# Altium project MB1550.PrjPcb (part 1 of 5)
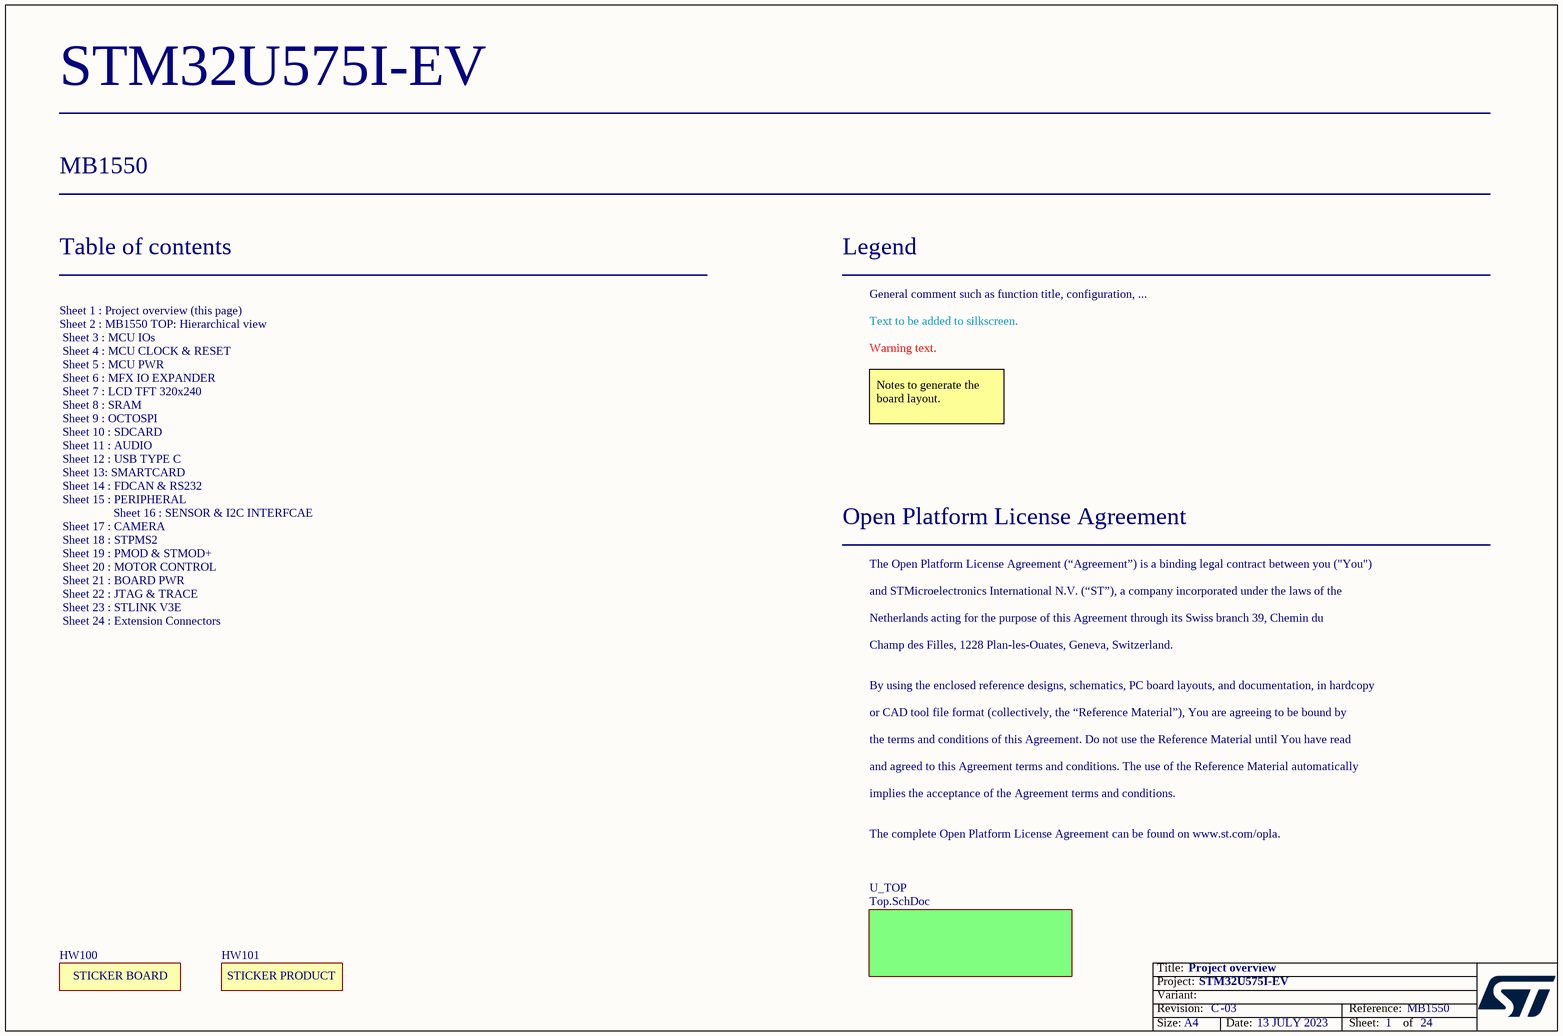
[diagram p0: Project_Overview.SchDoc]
Board_Assembly_Revision: 03; Board_Document_Date: 13 JULY 2023; Board_Name: STM32U575I-EV; Board_PCB_Revision: C; Board_Reference: MB1550
24 sheets, 831 parts. Net scope: flat (ports and power ports of the same name join across sheets).
Board file: MB1550.PcbDoc
Sheets:
  Project_Overview.SchDoc
    U_TOP = Top.SchDoc
      U_AUDIO = AUDIO.SchDoc
      U_BOARD_PWR = BOARD_PWR.SchDoc
      U_Extension_Connector = Extension_Connector.SchDoc
      U_FDCAN_RS232 = FDCAN_RS232.SchDoc
      U_JTAG_TRACE = JTAG_TRACE.SchDoc
      U_MCU_CLOCK_&_RESET = MCU_CLOCK_&_RESET.SchDoc
      U_MCU_IO = MCU_IO.SchDoc
      U_MCU_PWR = MCU_PWR.SchDoc
      U_MOTOR_CONTROL = MOTOR_CONTROL.SchDoc
      U_OCTOSPI = OCTOSPI.SchDoc
      U_PERIPHERAL = PERIPHERAL.SchDoc
      U_PMOD_STMOD+ = PMOD_STMOD+.SchDoc
      U_SDCARD = SDCARD.SchDoc
      U_SMARTCARD = SMARTCARD.SchDoc
      U_SRAM = SRAM.SchDoc
      U_USB_TYPEC = USB_TYPEC.SchDoc
      U_LCD_TFT_320x240 = LCD_TFT_320x240.SchDoc
      U_ST_LINK_V3E = ST_LINK_V3E.SchDoc
      U_Camera = Camera.SchDoc
      U_MFX_IO_expander = MFX_IO_expander.SchDoc
      U_STPMS2 = STPMS2.SchDoc
      U_SENSOR_and_I2C-interface = SENSOR_and_I2C-interface.SchDoc

## Sheet Project_Overview.SchDoc: Project overview
size A4; Date: Not used; ApprovedBy: Not used; CheckedBy: Not used; Author: Not used; CompanyName: STMicroelectronics; DrawnBy: Not used; Engineer: Not used; Organization: Not used; Address1: Not used; Address2: Not used; Address3: Not used; Address4: Not used; DocumentNumber: 1; Revision: Not used; SheetNumber: 1; SheetTotal: 24

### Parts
HW100  STICKER_BOARD  [STICKER_BOARD_25X9]  (value not drawn)  (no BOM)
HW101  STICKER_PRODUCT  [STICKER_PRODUCT_25X9]  (value not drawn)  (no BOM)

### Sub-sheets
U_TOP = Top.SchDoc: no entries

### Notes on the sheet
- Table of contents
- Legend
- General comment such as function title, configuration, ...
- Text to be added to silkscreen.
- Warning text.
- Notes to generate the board layout.
- Open Platform License Agreement
- The Open Platform License Agreement (“Agreement”) is a binding legal contract between you ("You")
- Sheet 1 : Project overview (this page)
  Sheet 2 : MB1550 TOP: Hierarchical view
  Sheet 3 : MCU IOs
  Sheet 4 : MCU CLOCK & RESET
  Sheet 5 : MCU PWR
  Sheet 6 : MFX IO EXPANDER
  Sheet 7 : LCD TFT 320x240
  Sheet 8 : SRAM
  Sheet 9 : OCTOSPI
  Sheet 10 : SDCARD
  Sheet 11 : AUDIO
  Sheet 12 : USB TYPE C
  Sheet 13: SMARTCARD
  Sheet 14 : FDCAN & RS232
  Sheet 15 : PERIPHERAL
  Sheet 16 : SENSOR & I2C INTERFCAE
  Sheet 17 : CAMERA
  Sheet 18 : STPMS2
  Sheet 19 : PMOD & STMOD+
  Sheet 20 : MOTOR CONTROL
  Sheet 21 : BOARD PWR
  Sheet 22 : JTAG & TRACE
  Sheet 23 : STLINK V3E
  Sheet 24 : Extension Connectors
- and STMicroelectronics International N.V. (“ST”), a company incorporated under the laws of the
- Netherlands acting for the purpose of this Agreement through its Swiss branch 39, Chemin du
- Champ des Filles, 1228 Plan-les-Ouates, Geneva, Switzerland.
- By using the enclosed reference designs, schematics, PC board layouts, and documentation, in hardcopy
- or CAD tool file format (collectively, the “Reference Material”), You are agreeing to be bound by
- the terms and conditions of this Agreement. Do not use the Reference Material until You have read
- and agreed to this Agreement terms and conditions. The use of the Reference Material automatically
- implies the acceptance of the Agreement terms and conditions.
- The complete Open Platform License Agreement can be found on www.st.com/opla.

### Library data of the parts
HW100 = MCD-00235: Sticker Board 25x9 mm; Part_Type: Misc; Part_Preference: Recommended
HW101 = MCD-00547: Sticker product 25x9 mm; Part_Type: Misc; Part_Preference: Recommended

## Sheet Top.SchDoc: TOP: Hierarchical view
size A3; Date: Not used; ApprovedBy: Not used; CheckedBy: Not used; Author: Not used; CompanyName: STMicroelectronics; DrawnBy: Not used; Engineer: Not used; Organization: Not used; Address1: Not used; Address2: Not used; Address3: Not used; Address4: Not used; DocumentNumber: 2; Revision: Not used; SheetNumber: 2; SheetTotal: 24
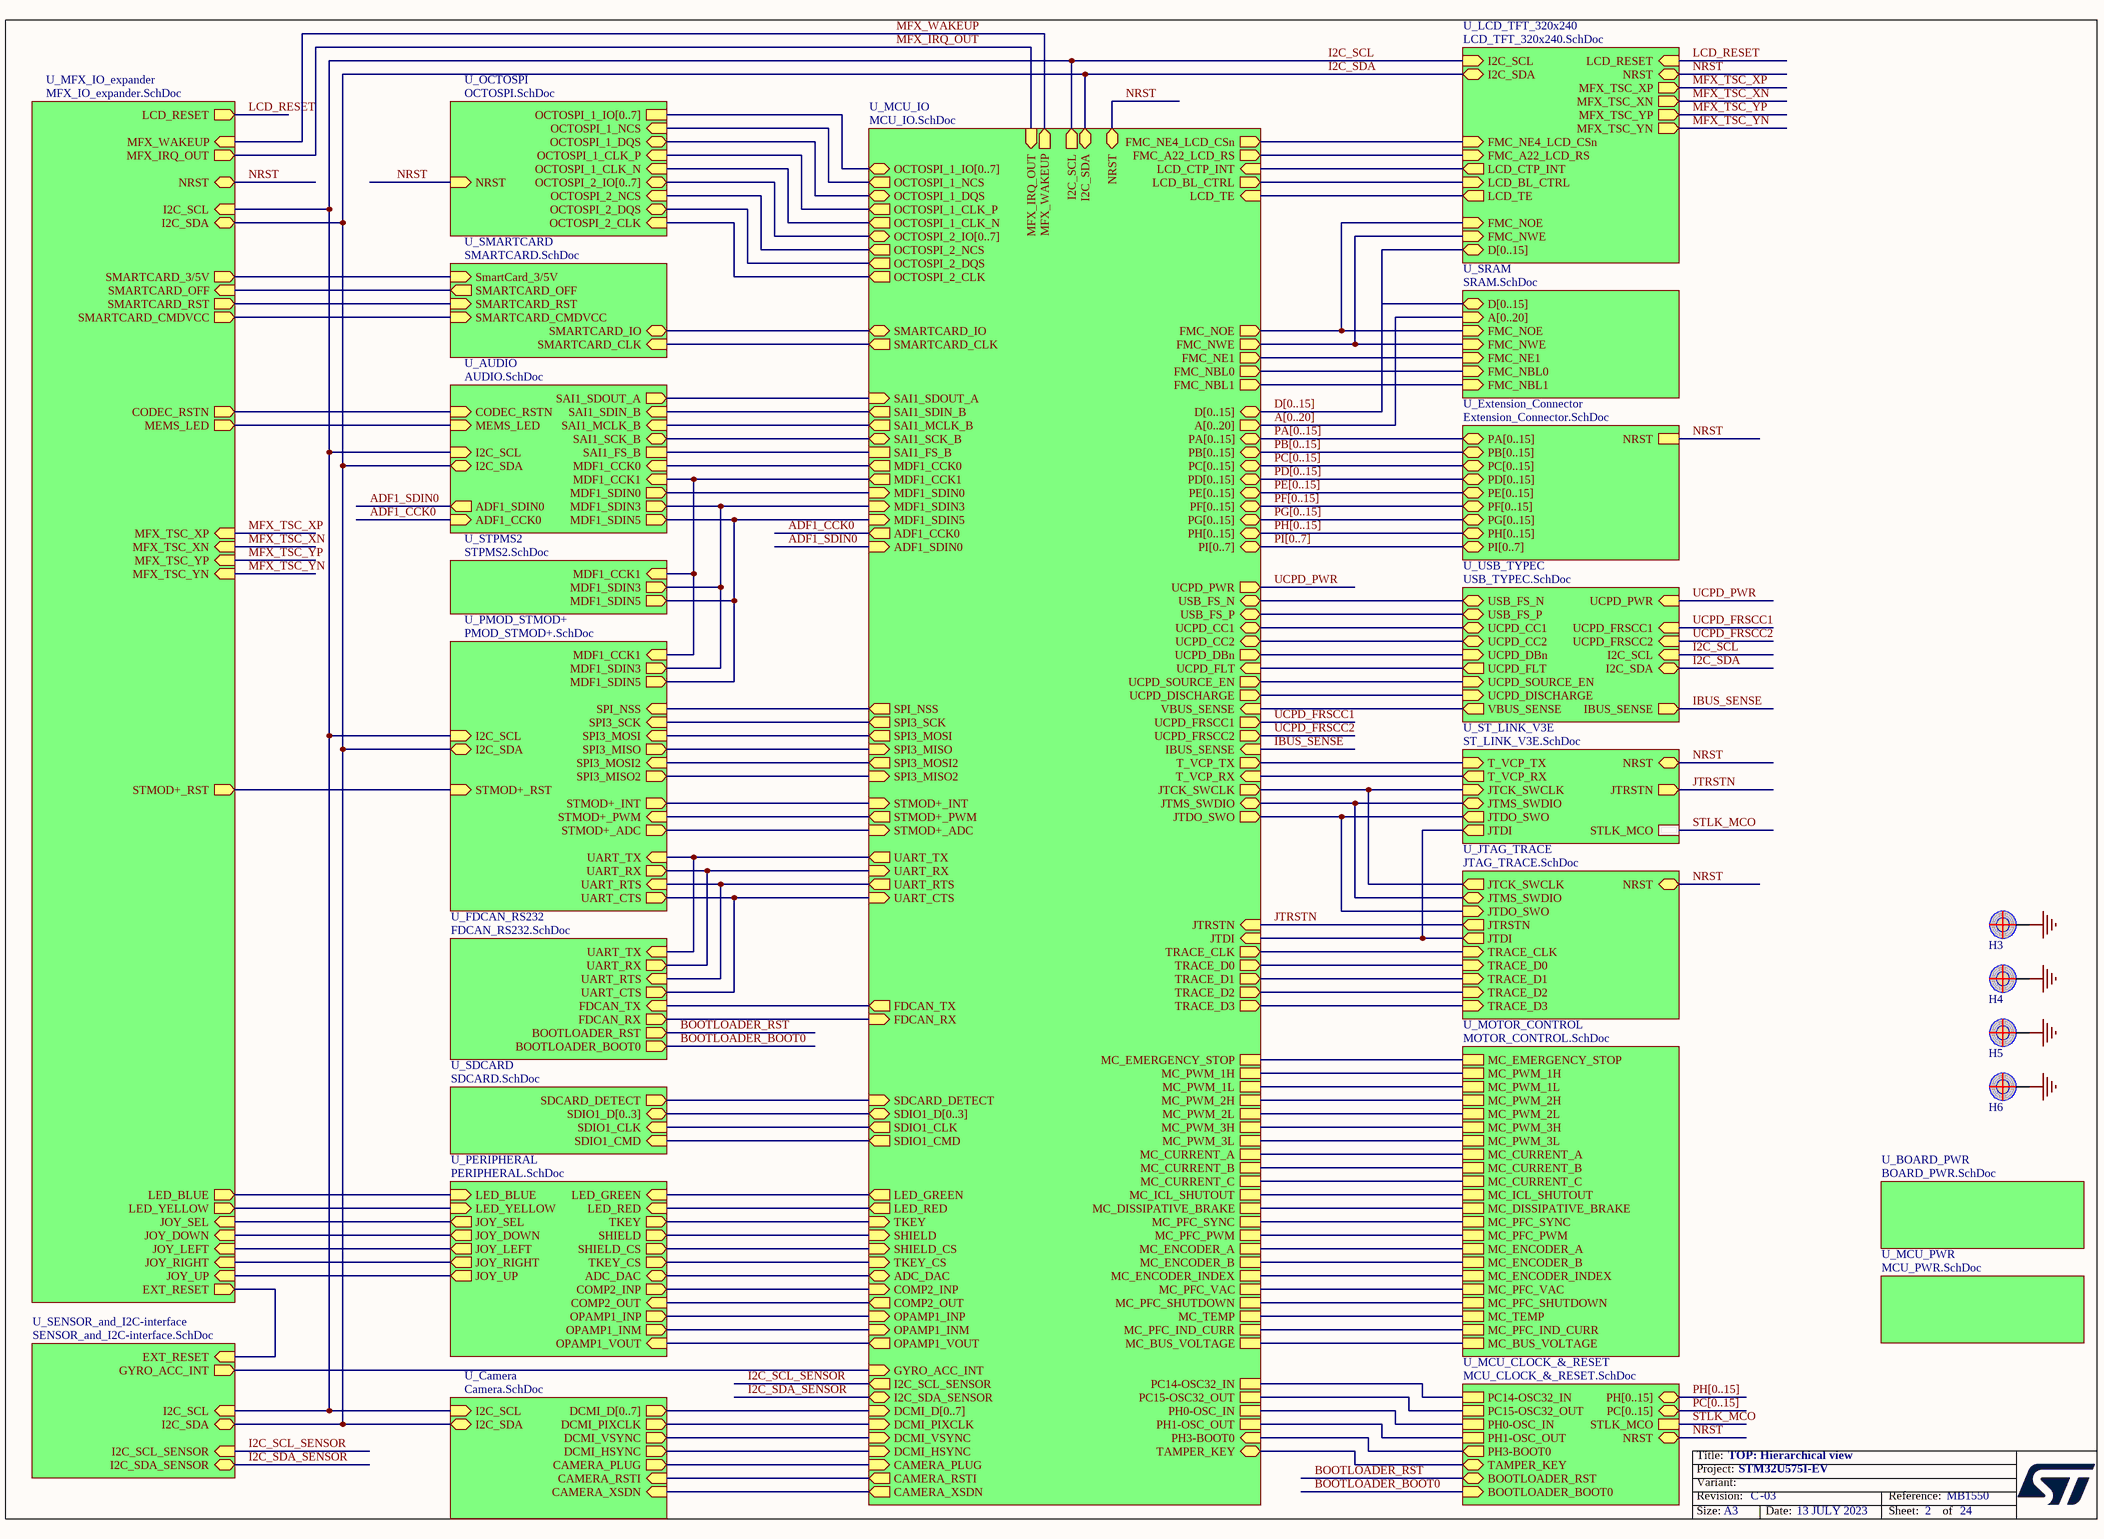
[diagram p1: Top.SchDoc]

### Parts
H3  (no value)  [PTH_M1261-3005-N_3P5X6_M3_H14]  (no BOM)
H4  (no value)  [PTH_M1261-3005-N_3P5X6_M3_H14]  (no BOM)
H5  (no value)  [PTH_M1261-3005-N_3P5X6_M3_H14]  (no BOM)
H6  (no value)  [PTH_M1261-3005-N_3P5X6_M3_H14]  (no BOM)

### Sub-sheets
U_AUDIO = AUDIO.SchDoc: SAI1_MCLK_B (in), SAI1_FS_B, CODEC_RSTN (in), ADF1_SDIN0 (out), MDF1_CCK0 (in), I2C_SCL (in), MEMS_LED (in), SAI1_SDOUT_A (out), MDF1_CCK1 (in), I2C_SDA (bidir), MDF1_SDIN0 (out), MDF1_SDIN5 (out), ADF1_CCK0 (in), SAI1_SCK_B (bidir), MDF1_SDIN3 (out), SAI1_SDIN_B (in)
U_BOARD_PWR = BOARD_PWR.SchDoc: no entries
U_Camera = Camera.SchDoc: DCMI_PIXCLK (out), DCMI_D[0..7] (out), I2C_SDA (bidir), I2C_SCL (in), DCMI_VSYNC (out), CAMERA_PLUG (out), DCMI_HSYNC (out), CAMERA_XSDN (in), CAMERA_RSTI (in)
U_Extension_Connector = Extension_Connector.SchDoc: PA[0..15] (bidir), PB[0..15] (bidir), PC[0..15] (bidir), NRST, PI[0..7] (bidir), PH[0..15] (bidir), PE[0..15] (bidir), PF[0..15] (bidir), PG[0..15] (bidir), PD[0..15] (bidir)
U_FDCAN_RS232 = FDCAN_RS232.SchDoc: BOOTLOADER_BOOT0 (out), BOOTLOADER_RST (out), FDCAN_RX (out), FDCAN_TX (in), UART_RX (out), UART_TX (in), UART_RTS (in), UART_CTS (out)
U_JTAG_TRACE = JTAG_TRACE.SchDoc: JTMS_SWDIO (bidir), JTDI (out), JTDO_SWO (in), JTRSTN (out), TRACE_CLK (in), TRACE_D0 (in), TRACE_D1 (in), TRACE_D2 (in), TRACE_D3 (in), JTCK_SWCLK (out), NRST (bidir)
U_LCD_TFT_320x240 = LCD_TFT_320x240.SchDoc: LCD_RESET (in), LCD_BL_CTRL (in), FMC_NOE (in), FMC_NWE (in), D[0..15] (bidir), LCD_TE (out), FMC_A22_LCD_RS (in), FMC_NE4_LCD_CSn (in), LCD_CTP_INT (out), MFX_TSC_YP (out), I2C_SCL (in), NRST (bidir), MFX_TSC_XP (out), MFX_TSC_YN (out), MFX_TSC_XN (out), I2C_SDA (bidir)
U_MCU_CLOCK_&_RESET = MCU_CLOCK_&_RESET.SchDoc: PC[0..15] (bidir), PH0-OSC_IN, PH1-OSC_OUT, PC14-OSC32_IN, PC15-OSC32_OUT, STLK_MCO, PH[0..15] (bidir), BOOTLOADER_RST (bidir), NRST (bidir), BOOTLOADER_BOOT0 (in), TAMPER_KEY (bidir), PH3-BOOT0 (out)
U_MCU_IO = MCU_IO.SchDoc: PA[0..15] (bidir), PB[0..15] (bidir), PC[0..15] (bidir), PH3-BOOT0 (in), PH0-OSC_IN, PH1-OSC_OUT, PC14-OSC32_IN, PC15-OSC32_OUT, JTMS_SWDIO (bidir), JTDI (in), JTDO_SWO (out), JTRSTN (in), T_VCP_TX (out), T_VCP_RX (in), MFX_IRQ_OUT (in), MFX_WAKEUP (out), D[0..15] (bidir), A[0..20] (out), LCD_BL_CTRL (out), TRACE_D0 (out), SPI3_MISO2 (in), TRACE_D1 (out), TRACE_CLK (out), TRACE_D2 (out), TRACE_D3 (out), SPI3_SCK (out), MC_ICL_SHUTOUT, FMC_NOE (out), FMC_NWE (out), FMC_NE1 (out), FMC_NBL0 (out), FMC_NBL1 (out), MC_PWM_3L, MC_PWM_2L, MC_PWM_1L, MC_PFC_VAC, MC_CURRENT_B, MC_CURRENT_C, MC_PFC_IND_CURR, MC_CURRENT_A, MC_DISSIPATIVE_BRAKE, MC_ENCODER_INDEX, MC_TEMP, SDIO1_CMD (out), SDIO1_CLK (out), SDIO1_D[0..3] (bidir), SDCARD_DETECT (in), MC_PWM_3H, SPI3_MOSI (out), SPI3_MISO (in), SAI1_MCLK_B (out), SAI1_SCK_B (bidir), SAI1_FS_B, MC_PFC_SYNC, MC_PFC_PWM, SPI3_MOSI2 (out), FDCAN_TX (out), FDCAN_RX (in), MC_PFC_SHUTDOWN, MC_PWM_1H, MC_PWM_2H, MC_EMERGENCY_STOP, COMP2_INP (in), COMP2_OUT (out), OPAMP1_INP (in), OPAMP1_VOUT (out), SPI_NSS (out), OPAMP1_INM (in), STMOD+_INT (in), MC_ENCODER_A, MC_ENCODER_B, MC_BUS_VOLTAGE, SMARTCARD_CLK (out), SMARTCARD_IO (bidir), UART_RX (in), UART_TX (out), UCPD_CC2 (bidir), UART_CTS (in), UART_RTS (out), MDF1_CCK1 (out), PI[0..7] (bidir), OCTOSPI_1_NCS (out), MDF1_SDIN0 (in), FMC_NE4_LCD_CSn (out), OCTOSPI_2_IO[0..7] (bidir), OCTOSPI_2_DQS (out), MDF1_SDIN5 (in), PH[0..15] (bidir), ADF1_CCK0 (out), MDF1_CCK0 (out), PG[0..15] (bidir), PF[0..15] (bidir), PE[0..15] (bidir), PD[0..15] (bidir), I2C_SCL (out), LED_GREEN (out), UCPD_SOURCE_EN (out), UCPD_DISCHARGE (out), GYRO_ACC_INT (in), OCTOSPI_1_CLK_P (out), I2C_SCL_SENSOR (out), USB_FS_P (bidir), TKEY (in), ADC_DAC (bidir), NRST (bidir), TAMPER_KEY (bidir), SHIELD (in), MDF1_SDIN3 (in), UCPD_DBn (out), UCPD_FLT (in), STMOD+_PWM (out), DCMI_HSYNC (in), UCPD_CC1 (bidir), I2C_SDA (bidir), TKEY_CS (in), STMOD+_ADC (in), FMC_A22_LCD_RS (out), SAI1_SDOUT_A (in), USB_FS_N (bidir), JTCK_SWCLK (out), OCTOSPI_1_DQS (bidir), SHIELD_CS (in), OCTOSPI_1_IO[0..7] (bidir), DCMI_D[0..7] (in), LCD_CTP_INT (in), SAI1_SDIN_B (out), VBUS_SENSE (in), LED_RED (out), CAMERA_XSDN (out), DCMI_VSYNC (in), UCPD_FRSCC1 (out), I2C_SDA_SENSOR (bidir), OCTOSPI_2_NCS (out), UCPD_PWR (out), UCPD_FRSCC2 (out), OCTOSPI_1_CLK_N (out), CAMERA_PLUG (in), OCTOSPI_2_CLK (out), ADF1_SDIN0 (in), LCD_TE (in), DCMI_PIXCLK (in), IBUS_SENSE (in), CAMERA_RSTI (out)
U_MCU_PWR = MCU_PWR.SchDoc: no entries
U_MFX_IO_expander = MFX_IO_expander.SchDoc: MFX_IRQ_OUT (out), MFX_WAKEUP (in), JOY_SEL (in), JOY_DOWN (in), JOY_LEFT (in), JOY_RIGHT (in), JOY_UP (in), LCD_RESET (out), EXT_RESET (out), STMOD+_RST (out), CODEC_RSTN (out), SMARTCARD_3/5V (out), SMARTCARD_CMDVCC (out), SMARTCARD_RST (out), SMARTCARD_OFF (in), MEMS_LED (out), MFX_TSC_XP (in), MFX_TSC_XN (in), MFX_TSC_YP (in), MFX_TSC_YN (in), LED_YELLOW (out), I2C_SCL (in), NRST (bidir), I2C_SDA (bidir), LED_BLUE (out)
U_MOTOR_CONTROL = MOTOR_CONTROL.SchDoc: MC_EMERGENCY_STOP, MC_PWM_1H, MC_PWM_1L, MC_PWM_2H, MC_PWM_2L, MC_PWM_3H, MC_PWM_3L, MC_CURRENT_A, MC_CURRENT_B, MC_CURRENT_C, MC_ICL_SHUTOUT, MC_DISSIPATIVE_BRAKE, MC_PFC_SYNC, MC_PFC_PWM, MC_ENCODER_A, MC_ENCODER_B, MC_ENCODER_INDEX, MC_PFC_VAC, MC_PFC_SHUTDOWN, MC_TEMP, MC_PFC_IND_CURR, MC_BUS_VOLTAGE
U_OCTOSPI = OCTOSPI.SchDoc: NRST (in), OCTOSPI_1_IO[0..7], OCTOSPI_1_NCS (in), OCTOSPI_2_NCS (in), OCTOSPI_2_IO[0..7] (bidir), OCTOSPI_2_CLK (in), OCTOSPI_1_CLK_N (in), OCTOSPI_1_CLK_P (in), OCTOSPI_1_DQS (bidir), OCTOSPI_2_DQS (bidir)
U_PERIPHERAL = PERIPHERAL.SchDoc: JOY_SEL (out), JOY_DOWN (out), JOY_LEFT (out), JOY_RIGHT (out), JOY_UP (out), COMP2_INP (out), OPAMP1_VOUT (in), OPAMP1_INM (out), OPAMP1_INP (out), COMP2_OUT (in), TKEY (out), ADC_DAC (bidir), LED_YELLOW (in), TKEY_CS (out), LED_BLUE (in), LED_GREEN (in), SHIELD (out), SHIELD_CS (out), LED_RED (in)
U_PMOD_STMOD+ = PMOD_STMOD+.SchDoc: STMOD+_INT (out), SPI_NSS (in), SPI3_MOSI (in), SPI3_MISO (out), SPI3_SCK (in), STMOD+_RST (in), SPI3_MOSI2 (in), SPI3_MISO2 (out), UART_RX (out), UART_TX (in), UART_RTS (in), UART_CTS (out), I2C_SCL (in), STMOD+_ADC (out), I2C_SDA (bidir), MDF1_SDIN5 (out), MDF1_SDIN3 (out), STMOD+_PWM (in), MDF1_CCK1 (in)
U_SDCARD = SDCARD.SchDoc: SDIO1_CMD (in), SDIO1_CLK (in), SDCARD_DETECT (out), SDIO1_D[0..3] (bidir)
U_SENSOR_and_I2C-interface = SENSOR_and_I2C-interface.SchDoc: I2C_SCL (in), EXT_RESET (in), GYRO_ACC_INT (out), I2C_SCL_SENSOR (in), I2C_SDA_SENSOR (bidir), I2C_SDA (bidir)
U_SMARTCARD = SMARTCARD.SchDoc: SmartCard_3/5V (in), SMARTCARD_IO (bidir), SMARTCARD_RST (in), SMARTCARD_CLK (in), SMARTCARD_OFF (out), SMARTCARD_CMDVCC (in)
U_SRAM = SRAM.SchDoc: FMC_NWE (in), FMC_NOE (in), FMC_NE1 (in), D[0..15] (bidir), A[0..20] (in), FMC_NBL0 (in), FMC_NBL1 (in)
U_ST_LINK_V3E = ST_LINK_V3E.SchDoc: STLK_MCO, JTMS_SWDIO (bidir), JTDO_SWO (out), JTCK_SWCLK (in), JTRSTN (out), T_VCP_RX (out), JTDI (out), T_VCP_TX (in), NRST (bidir)
U_STPMS2 = STPMS2.SchDoc: MDF1_CCK1 (in), MDF1_SDIN3 (out), MDF1_SDIN5 (out)
U_USB_TYPEC = USB_TYPEC.SchDoc: USB_FS_N (bidir), USB_FS_P (bidir), UCPD_PWR (in), I2C_SCL (in), I2C_SDA (bidir), UCPD_DISCHARGE (in), UCPD_DBn (in), UCPD_CC1 (bidir), UCPD_FRSCC2 (in), VBUS_SENSE (out), UCPD_FRSCC1 (in), UCPD_SOURCE_EN (in), IBUS_SENSE (out), UCPD_CC2 (bidir), UCPD_FLT (out)

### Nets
GND: H3.1 H4.1 H5.1 H6.1
ADF1_CCK0: sheet U_AUDIO/ADF1_CCK0, sheet U_MCU_IO/ADF1_CCK0
ADF1_SDIN0: sheet U_AUDIO/ADF1_SDIN0, sheet U_MCU_IO/ADF1_SDIN0
BOOTLOADER_BOOT0: sheet U_FDCAN_RS232/BOOTLOADER_BOOT0, sheet U_MCU_CLOCK_&_RESET/BOOTLOADER_BOOT0
BOOTLOADER_RST: sheet U_FDCAN_RS232/BOOTLOADER_RST, sheet U_MCU_CLOCK_&_RESET/BOOTLOADER_RST
I2C_SCL: sheet U_AUDIO/I2C_SCL, sheet U_MCU_IO/I2C_SCL, sheet U_PMOD_STMOD+/I2C_SCL, sheet U_USB_TYPEC/I2C_SCL, sheet U_LCD_TFT_320x240/I2C_SCL, sheet U_Camera/I2C_SCL, sheet U_MFX_IO_expander/I2C_SCL, sheet U_SENSOR_and_I2C-interface/I2C_SCL
I2C_SCL_SENSOR: sheet U_MCU_IO/I2C_SCL_SENSOR, sheet U_SENSOR_and_I2C-interface/I2C_SCL_SENSOR
I2C_SDA: sheet U_AUDIO/I2C_SDA, sheet U_MCU_IO/I2C_SDA, sheet U_PMOD_STMOD+/I2C_SDA, sheet U_USB_TYPEC/I2C_SDA, sheet U_LCD_TFT_320x240/I2C_SDA, sheet U_Camera/I2C_SDA, sheet U_MFX_IO_expander/I2C_SDA, sheet U_SENSOR_and_I2C-interface/I2C_SDA
I2C_SDA_SENSOR: sheet U_MCU_IO/I2C_SDA_SENSOR, sheet U_SENSOR_and_I2C-interface/I2C_SDA_SENSOR
IBUS_SENSE: sheet U_MCU_IO/IBUS_SENSE, sheet U_USB_TYPEC/IBUS_SENSE
JTRSTN: sheet U_JTAG_TRACE/JTRSTN, sheet U_MCU_IO/JTRSTN, sheet U_ST_LINK_V3E/JTRSTN
LCD_RESET: sheet U_LCD_TFT_320x240/LCD_RESET, sheet U_MFX_IO_expander/LCD_RESET
MFX_IRQ_OUT: sheet U_MCU_IO/MFX_IRQ_OUT, sheet U_MFX_IO_expander/MFX_IRQ_OUT
MFX_TSC_XN: sheet U_LCD_TFT_320x240/MFX_TSC_XN, sheet U_MFX_IO_expander/MFX_TSC_XN
MFX_TSC_XP: sheet U_LCD_TFT_320x240/MFX_TSC_XP, sheet U_MFX_IO_expander/MFX_TSC_XP
MFX_TSC_YN: sheet U_LCD_TFT_320x240/MFX_TSC_YN, sheet U_MFX_IO_expander/MFX_TSC_YN
MFX_TSC_YP: sheet U_LCD_TFT_320x240/MFX_TSC_YP, sheet U_MFX_IO_expander/MFX_TSC_YP
MFX_WAKEUP: sheet U_MCU_IO/MFX_WAKEUP, sheet U_MFX_IO_expander/MFX_WAKEUP
NRST: sheet U_Extension_Connector/NRST, sheet U_JTAG_TRACE/NRST, sheet U_MCU_CLOCK_&_RESET/NRST, sheet U_MCU_IO/NRST, sheet U_OCTOSPI/NRST, sheet U_LCD_TFT_320x240/NRST, sheet U_ST_LINK_V3E/NRST, sheet U_MFX_IO_expander/NRST
STLK_MCO: sheet U_MCU_CLOCK_&_RESET/STLK_MCO, sheet U_ST_LINK_V3E/STLK_MCO
UCPD_FRSCC1: sheet U_MCU_IO/UCPD_FRSCC1, sheet U_USB_TYPEC/UCPD_FRSCC1
UCPD_FRSCC2: sheet U_MCU_IO/UCPD_FRSCC2, sheet U_USB_TYPEC/UCPD_FRSCC2
UCPD_PWR: sheet U_MCU_IO/UCPD_PWR, sheet U_USB_TYPEC/UCPD_PWR
(unnamed): sheet U_AUDIO/SAI1_MCLK_B, sheet U_MCU_IO/SAI1_MCLK_B
(unnamed): sheet U_AUDIO/SAI1_FS_B, sheet U_MCU_IO/SAI1_FS_B  [a separate net that carries the same name]
(unnamed): sheet U_AUDIO/CODEC_RSTN, sheet U_MFX_IO_expander/CODEC_RSTN  [a separate net that carries the same name]
(unnamed): sheet U_AUDIO/MDF1_CCK0, sheet U_MCU_IO/MDF1_CCK0  [a separate net that carries the same name]
(unnamed): sheet U_AUDIO/MEMS_LED, sheet U_MFX_IO_expander/MEMS_LED  [a separate net that carries the same name]
(unnamed): sheet U_AUDIO/SAI1_SDOUT_A, sheet U_MCU_IO/SAI1_SDOUT_A  [a separate net that carries the same name]
(unnamed): sheet U_AUDIO/MDF1_CCK1, sheet U_MCU_IO/MDF1_CCK1, sheet U_PMOD_STMOD+/MDF1_CCK1, sheet U_STPMS2/MDF1_CCK1  [a separate net that carries the same name]
(unnamed): sheet U_AUDIO/MDF1_SDIN0, sheet U_MCU_IO/MDF1_SDIN0  [a separate net that carries the same name]
(unnamed): sheet U_AUDIO/MDF1_SDIN5, sheet U_MCU_IO/MDF1_SDIN5, sheet U_PMOD_STMOD+/MDF1_SDIN5, sheet U_STPMS2/MDF1_SDIN5  [a separate net that carries the same name]
(unnamed): sheet U_AUDIO/SAI1_SCK_B, sheet U_MCU_IO/SAI1_SCK_B  [a separate net that carries the same name]
(unnamed): sheet U_AUDIO/MDF1_SDIN3, sheet U_MCU_IO/MDF1_SDIN3, sheet U_PMOD_STMOD+/MDF1_SDIN3, sheet U_STPMS2/MDF1_SDIN3  [a separate net that carries the same name]
(unnamed): sheet U_AUDIO/SAI1_SDIN_B, sheet U_MCU_IO/SAI1_SDIN_B  [a separate net that carries the same name]
(unnamed): sheet U_FDCAN_RS232/FDCAN_RX, sheet U_MCU_IO/FDCAN_RX  [a separate net that carries the same name]
(unnamed): sheet U_FDCAN_RS232/FDCAN_TX, sheet U_MCU_IO/FDCAN_TX  [a separate net that carries the same name]
(unnamed): sheet U_FDCAN_RS232/UART_RX, sheet U_MCU_IO/UART_RX, sheet U_PMOD_STMOD+/UART_RX  [a separate net that carries the same name]
(unnamed): sheet U_FDCAN_RS232/UART_TX, sheet U_MCU_IO/UART_TX, sheet U_PMOD_STMOD+/UART_TX  [a separate net that carries the same name]
(unnamed): sheet U_FDCAN_RS232/UART_RTS, sheet U_MCU_IO/UART_RTS, sheet U_PMOD_STMOD+/UART_RTS  [a separate net that carries the same name]
(unnamed): sheet U_FDCAN_RS232/UART_CTS, sheet U_MCU_IO/UART_CTS, sheet U_PMOD_STMOD+/UART_CTS  [a separate net that carries the same name]
(unnamed): sheet U_JTAG_TRACE/JTMS_SWDIO, sheet U_MCU_IO/JTMS_SWDIO, sheet U_ST_LINK_V3E/JTMS_SWDIO  [a separate net that carries the same name]
(unnamed): sheet U_JTAG_TRACE/JTDI, sheet U_MCU_IO/JTDI, sheet U_ST_LINK_V3E/JTDI  [a separate net that carries the same name]
(unnamed): sheet U_JTAG_TRACE/JTDO_SWO, sheet U_MCU_IO/JTDO_SWO, sheet U_ST_LINK_V3E/JTDO_SWO  [a separate net that carries the same name]
(unnamed): sheet U_JTAG_TRACE/TRACE_CLK, sheet U_MCU_IO/TRACE_CLK  [a separate net that carries the same name]
(unnamed): sheet U_JTAG_TRACE/TRACE_D0, sheet U_MCU_IO/TRACE_D0  [a separate net that carries the same name]
(unnamed): sheet U_JTAG_TRACE/TRACE_D1, sheet U_MCU_IO/TRACE_D1  [a separate net that carries the same name]
(unnamed): sheet U_JTAG_TRACE/TRACE_D2, sheet U_MCU_IO/TRACE_D2  [a separate net that carries the same name]
(unnamed): sheet U_JTAG_TRACE/TRACE_D3, sheet U_MCU_IO/TRACE_D3  [a separate net that carries the same name]
(unnamed): sheet U_JTAG_TRACE/JTCK_SWCLK, sheet U_MCU_IO/JTCK_SWCLK, sheet U_ST_LINK_V3E/JTCK_SWCLK  [a separate net that carries the same name]
(unnamed): sheet U_MCU_CLOCK_&_RESET/PH0-OSC_IN, sheet U_MCU_IO/PH0-OSC_IN  [a separate net that carries the same name]
(unnamed): sheet U_MCU_CLOCK_&_RESET/PH1-OSC_OUT, sheet U_MCU_IO/PH1-OSC_OUT  [a separate net that carries the same name]
(unnamed): sheet U_MCU_CLOCK_&_RESET/PC14-OSC32_IN, sheet U_MCU_IO/PC14-OSC32_IN  [a separate net that carries the same name]
(unnamed): sheet U_MCU_CLOCK_&_RESET/PC15-OSC32_OUT, sheet U_MCU_IO/PC15-OSC32_OUT  [a separate net that carries the same name]
(unnamed): sheet U_MCU_CLOCK_&_RESET/TAMPER_KEY, sheet U_MCU_IO/TAMPER_KEY  [a separate net that carries the same name]
(unnamed): sheet U_MCU_CLOCK_&_RESET/PH3-BOOT0, sheet U_MCU_IO/PH3-BOOT0  [a separate net that carries the same name]
(unnamed): sheet U_MCU_IO/T_VCP_TX, sheet U_ST_LINK_V3E/T_VCP_TX  [a separate net that carries the same name]
(unnamed): sheet U_MCU_IO/T_VCP_RX, sheet U_ST_LINK_V3E/T_VCP_RX  [a separate net that carries the same name]
(unnamed): sheet U_MCU_IO/LCD_BL_CTRL, sheet U_LCD_TFT_320x240/LCD_BL_CTRL  [a separate net that carries the same name]
(unnamed): sheet U_MCU_IO/SPI3_MISO2, sheet U_PMOD_STMOD+/SPI3_MISO2  [a separate net that carries the same name]
(unnamed): sheet U_MCU_IO/SPI3_SCK, sheet U_PMOD_STMOD+/SPI3_SCK  [a separate net that carries the same name]
(unnamed): sheet U_MCU_IO/MC_ICL_SHUTOUT, sheet U_MOTOR_CONTROL/MC_ICL_SHUTOUT  [a separate net that carries the same name]
(unnamed): sheet U_MCU_IO/FMC_NOE, sheet U_SRAM/FMC_NOE, sheet U_LCD_TFT_320x240/FMC_NOE  [a separate net that carries the same name]
(unnamed): sheet U_MCU_IO/FMC_NWE, sheet U_SRAM/FMC_NWE, sheet U_LCD_TFT_320x240/FMC_NWE  [a separate net that carries the same name]
(unnamed): sheet U_MCU_IO/FMC_NE1, sheet U_SRAM/FMC_NE1  [a separate net that carries the same name]
(unnamed): sheet U_MCU_IO/FMC_NBL0, sheet U_SRAM/FMC_NBL0  [a separate net that carries the same name]
(unnamed): sheet U_MCU_IO/FMC_NBL1, sheet U_SRAM/FMC_NBL1  [a separate net that carries the same name]
(unnamed): sheet U_MCU_IO/MC_PWM_3L, sheet U_MOTOR_CONTROL/MC_PWM_3L  [a separate net that carries the same name]
(unnamed): sheet U_MCU_IO/MC_PWM_2L, sheet U_MOTOR_CONTROL/MC_PWM_2L  [a separate net that carries the same name]
(unnamed): sheet U_MCU_IO/MC_PWM_1L, sheet U_MOTOR_CONTROL/MC_PWM_1L  [a separate net that carries the same name]
(unnamed): sheet U_MCU_IO/MC_PFC_VAC, sheet U_MOTOR_CONTROL/MC_PFC_VAC  [a separate net that carries the same name]
(unnamed): sheet U_MCU_IO/MC_CURRENT_B, sheet U_MOTOR_CONTROL/MC_CURRENT_B  [a separate net that carries the same name]
(unnamed): sheet U_MCU_IO/MC_CURRENT_C, sheet U_MOTOR_CONTROL/MC_CURRENT_C  [a separate net that carries the same name]
(unnamed): sheet U_MCU_IO/MC_PFC_IND_CURR, sheet U_MOTOR_CONTROL/MC_PFC_IND_CURR  [a separate net that carries the same name]
(unnamed): sheet U_MCU_IO/MC_CURRENT_A, sheet U_MOTOR_CONTROL/MC_CURRENT_A  [a separate net that carries the same name]
(unnamed): sheet U_MCU_IO/MC_DISSIPATIVE_BRAKE, sheet U_MOTOR_CONTROL/MC_DISSIPATIVE_BRAKE  [a separate net that carries the same name]
(unnamed): sheet U_MCU_IO/MC_ENCODER_INDEX, sheet U_MOTOR_CONTROL/MC_ENCODER_INDEX  [a separate net that carries the same name]
(unnamed): sheet U_MCU_IO/MC_TEMP, sheet U_MOTOR_CONTROL/MC_TEMP  [a separate net that carries the same name]
(unnamed): sheet U_MCU_IO/SDIO1_CMD, sheet U_SDCARD/SDIO1_CMD  [a separate net that carries the same name]
(unnamed): sheet U_MCU_IO/SDIO1_CLK, sheet U_SDCARD/SDIO1_CLK  [a separate net that carries the same name]
(unnamed): sheet U_MCU_IO/SDCARD_DETECT, sheet U_SDCARD/SDCARD_DETECT  [a separate net that carries the same name]
(unnamed): sheet U_MCU_IO/MC_PWM_3H, sheet U_MOTOR_CONTROL/MC_PWM_3H  [a separate net that carries the same name]
(unnamed): sheet U_MCU_IO/SPI3_MOSI, sheet U_PMOD_STMOD+/SPI3_MOSI  [a separate net that carries the same name]
(unnamed): sheet U_MCU_IO/SPI3_MISO, sheet U_PMOD_STMOD+/SPI3_MISO  [a separate net that carries the same name]
(unnamed): sheet U_MCU_IO/MC_PFC_SYNC, sheet U_MOTOR_CONTROL/MC_PFC_SYNC  [a separate net that carries the same name]
(unnamed): sheet U_MCU_IO/MC_PFC_PWM, sheet U_MOTOR_CONTROL/MC_PFC_PWM  [a separate net that carries the same name]
(unnamed): sheet U_MCU_IO/SPI3_MOSI2, sheet U_PMOD_STMOD+/SPI3_MOSI2  [a separate net that carries the same name]
(unnamed): sheet U_MCU_IO/MC_PFC_SHUTDOWN, sheet U_MOTOR_CONTROL/MC_PFC_SHUTDOWN  [a separate net that carries the same name]
(unnamed): sheet U_MCU_IO/MC_PWM_1H, sheet U_MOTOR_CONTROL/MC_PWM_1H  [a separate net that carries the same name]
(unnamed): sheet U_MCU_IO/MC_PWM_2H, sheet U_MOTOR_CONTROL/MC_PWM_2H  [a separate net that carries the same name]
(unnamed): sheet U_MCU_IO/MC_EMERGENCY_STOP, sheet U_MOTOR_CONTROL/MC_EMERGENCY_STOP  [a separate net that carries the same name]
(unnamed): sheet U_MCU_IO/COMP2_INP, sheet U_PERIPHERAL/COMP2_INP  [a separate net that carries the same name]
(unnamed): sheet U_MCU_IO/COMP2_OUT, sheet U_PERIPHERAL/COMP2_OUT  [a separate net that carries the same name]
(unnamed): sheet U_MCU_IO/OPAMP1_INP, sheet U_PERIPHERAL/OPAMP1_INP  [a separate net that carries the same name]
(unnamed): sheet U_MCU_IO/OPAMP1_VOUT, sheet U_PERIPHERAL/OPAMP1_VOUT  [a separate net that carries the same name]
(unnamed): sheet U_MCU_IO/SPI_NSS, sheet U_PMOD_STMOD+/SPI_NSS  [a separate net that carries the same name]
(unnamed): sheet U_MCU_IO/OPAMP1_INM, sheet U_PERIPHERAL/OPAMP1_INM  [a separate net that carries the same name]
(unnamed): sheet U_MCU_IO/STMOD+_INT, sheet U_PMOD_STMOD+/STMOD+_INT  [a separate net that carries the same name]
(unnamed): sheet U_MCU_IO/MC_ENCODER_A, sheet U_MOTOR_CONTROL/MC_ENCODER_A  [a separate net that carries the same name]
(unnamed): sheet U_MCU_IO/MC_ENCODER_B, sheet U_MOTOR_CONTROL/MC_ENCODER_B  [a separate net that carries the same name]
(unnamed): sheet U_MCU_IO/MC_BUS_VOLTAGE, sheet U_MOTOR_CONTROL/MC_BUS_VOLTAGE  [a separate net that carries the same name]
(unnamed): sheet U_MCU_IO/SMARTCARD_CLK, sheet U_SMARTCARD/SMARTCARD_CLK  [a separate net that carries the same name]
(unnamed): sheet U_MCU_IO/SMARTCARD_IO, sheet U_SMARTCARD/SMARTCARD_IO  [a separate net that carries the same name]
(unnamed): sheet U_MCU_IO/UCPD_CC2, sheet U_USB_TYPEC/UCPD_CC2  [a separate net that carries the same name]
(unnamed): sheet U_MCU_IO/OCTOSPI_1_NCS, sheet U_OCTOSPI/OCTOSPI_1_NCS  [a separate net that carries the same name]
(unnamed): sheet U_MCU_IO/FMC_NE4_LCD_CSn, sheet U_LCD_TFT_320x240/FMC_NE4_LCD_CSn  [a separate net that carries the same name]
(unnamed): sheet U_MCU_IO/OCTOSPI_2_DQS, sheet U_OCTOSPI/OCTOSPI_2_DQS  [a separate net that carries the same name]
(unnamed): sheet U_MCU_IO/LED_GREEN, sheet U_PERIPHERAL/LED_GREEN  [a separate net that carries the same name]
(unnamed): sheet U_MCU_IO/UCPD_SOURCE_EN, sheet U_USB_TYPEC/UCPD_SOURCE_EN  [a separate net that carries the same name]
(unnamed): sheet U_MCU_IO/UCPD_DISCHARGE, sheet U_USB_TYPEC/UCPD_DISCHARGE  [a separate net that carries the same name]
(unnamed): sheet U_MCU_IO/GYRO_ACC_INT, sheet U_SENSOR_and_I2C-interface/GYRO_ACC_INT  [a separate net that carries the same name]
(unnamed): sheet U_MCU_IO/OCTOSPI_1_CLK_P, sheet U_OCTOSPI/OCTOSPI_1_CLK_P  [a separate net that carries the same name]
(unnamed): sheet U_MCU_IO/USB_FS_P, sheet U_USB_TYPEC/USB_FS_P  [a separate net that carries the same name]
(unnamed): sheet U_MCU_IO/TKEY, sheet U_PERIPHERAL/TKEY  [a separate net that carries the same name]
(unnamed): sheet U_MCU_IO/ADC_DAC, sheet U_PERIPHERAL/ADC_DAC  [a separate net that carries the same name]
(unnamed): sheet U_MCU_IO/SHIELD, sheet U_PERIPHERAL/SHIELD  [a separate net that carries the same name]
(unnamed): sheet U_MCU_IO/UCPD_DBn, sheet U_USB_TYPEC/UCPD_DBn  [a separate net that carries the same name]
(unnamed): sheet U_MCU_IO/UCPD_FLT, sheet U_USB_TYPEC/UCPD_FLT  [a separate net that carries the same name]
(unnamed): sheet U_MCU_IO/STMOD+_PWM, sheet U_PMOD_STMOD+/STMOD+_PWM  [a separate net that carries the same name]
(unnamed): sheet U_MCU_IO/DCMI_HSYNC, sheet U_Camera/DCMI_HSYNC  [a separate net that carries the same name]
(unnamed): sheet U_MCU_IO/UCPD_CC1, sheet U_USB_TYPEC/UCPD_CC1  [a separate net that carries the same name]
(unnamed): sheet U_MCU_IO/TKEY_CS, sheet U_PERIPHERAL/TKEY_CS  [a separate net that carries the same name]
(unnamed): sheet U_MCU_IO/STMOD+_ADC, sheet U_PMOD_STMOD+/STMOD+_ADC  [a separate net that carries the same name]
(unnamed): sheet U_MCU_IO/FMC_A22_LCD_RS, sheet U_LCD_TFT_320x240/FMC_A22_LCD_RS  [a separate net that carries the same name]
(unnamed): sheet U_MCU_IO/USB_FS_N, sheet U_USB_TYPEC/USB_FS_N  [a separate net that carries the same name]
(unnamed): sheet U_MCU_IO/OCTOSPI_1_DQS, sheet U_OCTOSPI/OCTOSPI_1_DQS  [a separate net that carries the same name]
(unnamed): sheet U_MCU_IO/SHIELD_CS, sheet U_PERIPHERAL/SHIELD_CS  [a separate net that carries the same name]
(unnamed): sheet U_MCU_IO/LCD_CTP_INT, sheet U_LCD_TFT_320x240/LCD_CTP_INT  [a separate net that carries the same name]
(unnamed): sheet U_MCU_IO/VBUS_SENSE, sheet U_USB_TYPEC/VBUS_SENSE  [a separate net that carries the same name]
(unnamed): sheet U_MCU_IO/LED_RED, sheet U_PERIPHERAL/LED_RED  [a separate net that carries the same name]
(unnamed): sheet U_MCU_IO/CAMERA_XSDN, sheet U_Camera/CAMERA_XSDN  [a separate net that carries the same name]
(unnamed): sheet U_MCU_IO/DCMI_VSYNC, sheet U_Camera/DCMI_VSYNC  [a separate net that carries the same name]
(unnamed): sheet U_MCU_IO/OCTOSPI_2_NCS, sheet U_OCTOSPI/OCTOSPI_2_NCS  [a separate net that carries the same name]
(unnamed): sheet U_MCU_IO/OCTOSPI_1_CLK_N, sheet U_OCTOSPI/OCTOSPI_1_CLK_N  [a separate net that carries the same name]
(unnamed): sheet U_MCU_IO/CAMERA_PLUG, sheet U_Camera/CAMERA_PLUG  [a separate net that carries the same name]
(unnamed): sheet U_MCU_IO/OCTOSPI_2_CLK, sheet U_OCTOSPI/OCTOSPI_2_CLK  [a separate net that carries the same name]
(unnamed): sheet U_MCU_IO/LCD_TE, sheet U_LCD_TFT_320x240/LCD_TE  [a separate net that carries the same name]
(unnamed): sheet U_MCU_IO/DCMI_PIXCLK, sheet U_Camera/DCMI_PIXCLK  [a separate net that carries the same name]
(unnamed): sheet U_MCU_IO/CAMERA_RSTI, sheet U_Camera/CAMERA_RSTI  [a separate net that carries the same name]
(unnamed): sheet U_PERIPHERAL/JOY_SEL, sheet U_MFX_IO_expander/JOY_SEL  [a separate net that carries the same name]
(unnamed): sheet U_PERIPHERAL/JOY_DOWN, sheet U_MFX_IO_expander/JOY_DOWN  [a separate net that carries the same name]
(unnamed): sheet U_PERIPHERAL/JOY_LEFT, sheet U_MFX_IO_expander/JOY_LEFT  [a separate net that carries the same name]
(unnamed): sheet U_PERIPHERAL/JOY_RIGHT, sheet U_MFX_IO_expander/JOY_RIGHT  [a separate net that carries the same name]
(unnamed): sheet U_PERIPHERAL/JOY_UP, sheet U_MFX_IO_expander/JOY_UP  [a separate net that carries the same name]
(unnamed): sheet U_PERIPHERAL/LED_YELLOW, sheet U_MFX_IO_expander/LED_YELLOW  [a separate net that carries the same name]
(unnamed): sheet U_PERIPHERAL/LED_BLUE, sheet U_MFX_IO_expander/LED_BLUE  [a separate net that carries the same name]
(unnamed): sheet U_PMOD_STMOD+/STMOD+_RST, sheet U_MFX_IO_expander/STMOD+_RST  [a separate net that carries the same name]
(unnamed): sheet U_SMARTCARD/SmartCard_3/5V, sheet U_MFX_IO_expander/SMARTCARD_3/5V  [a separate net that carries the same name]
(unnamed): sheet U_SMARTCARD/SMARTCARD_RST, sheet U_MFX_IO_expander/SMARTCARD_RST  [a separate net that carries the same name]
(unnamed): sheet U_SMARTCARD/SMARTCARD_OFF, sheet U_MFX_IO_expander/SMARTCARD_OFF  [a separate net that carries the same name]
(unnamed): sheet U_SMARTCARD/SMARTCARD_CMDVCC, sheet U_MFX_IO_expander/SMARTCARD_CMDVCC  [a separate net that carries the same name]
(unnamed): sheet U_MFX_IO_expander/EXT_RESET, sheet U_SENSOR_and_I2C-interface/EXT_RESET  [a separate net that carries the same name]

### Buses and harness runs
bus A[0..20] = sheet U_MCU_IO/A[0..20] = sheet U_SRAM/A[0..20]
bus D[0..15] = sheet U_LCD_TFT_320x240/D[0..15] = sheet U_MCU_IO/D[0..15] = sheet U_SRAM/D[0..15]
bus PA[0..15] = sheet U_Extension_Connector/PA[0..15] = sheet U_MCU_IO/PA[0..15]
bus PB[0..15] = sheet U_Extension_Connector/PB[0..15] = sheet U_MCU_IO/PB[0..15]
bus PC[0..15] = sheet U_Extension_Connector/PC[0..15] = sheet U_MCU_IO/PC[0..15]
bus PC[0..15] = sheet U_MCU_CLOCK_&_RESET/PC[0..15]
bus PD[0..15] = sheet U_Extension_Connector/PD[0..15] = sheet U_MCU_IO/PD[0..15]
bus PE[0..15] = sheet U_Extension_Connector/PE[0..15] = sheet U_MCU_IO/PE[0..15]
bus PF[0..15] = sheet U_Extension_Connector/PF[0..15] = sheet U_MCU_IO/PF[0..15]
bus PG[0..15] = sheet U_Extension_Connector/PG[0..15] = sheet U_MCU_IO/PG[0..15]
bus PH[0..15] = sheet U_Extension_Connector/PH[0..15] = sheet U_MCU_IO/PH[0..15]
bus PH[0..15] = sheet U_MCU_CLOCK_&_RESET/PH[0..15]
bus PI[0..7] = sheet U_Extension_Connector/PI[0..7] = sheet U_MCU_IO/PI[0..7]
bus sheet U_Camera/DCMI_D[0..7] = sheet U_MCU_IO/DCMI_D[0..7]
bus sheet U_MCU_IO/OCTOSPI_1_IO[0..7] = sheet U_OCTOSPI/OCTOSPI_1_IO[0..7]
bus sheet U_MCU_IO/OCTOSPI_2_IO[0..7] = sheet U_OCTOSPI/OCTOSPI_2_IO[0..7]
bus sheet U_MCU_IO/SDIO1_D[0..3] = sheet U_SDCARD/SDIO1_D[0..3]

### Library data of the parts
H3-H6 = MCD-00035: POSITION HOLE C6D3R5; Part_Type: Mechanical; Initial_Board_Reference: MB1274

## Sheet AUDIO.SchDoc: AUDIO
size A4; Date: Not used; ApprovedBy: Not used; CheckedBy: Not used; Author: Not used; CompanyName: STMicroelectronics; DrawnBy: Not used; Engineer: Not used; Organization: Not used; Address1: Not used; Address2: Not used; Address3: Not used; Address4: Not used; DocumentNumber: 11; Revision: Not used; SheetNumber: 11; SheetTotal: 24
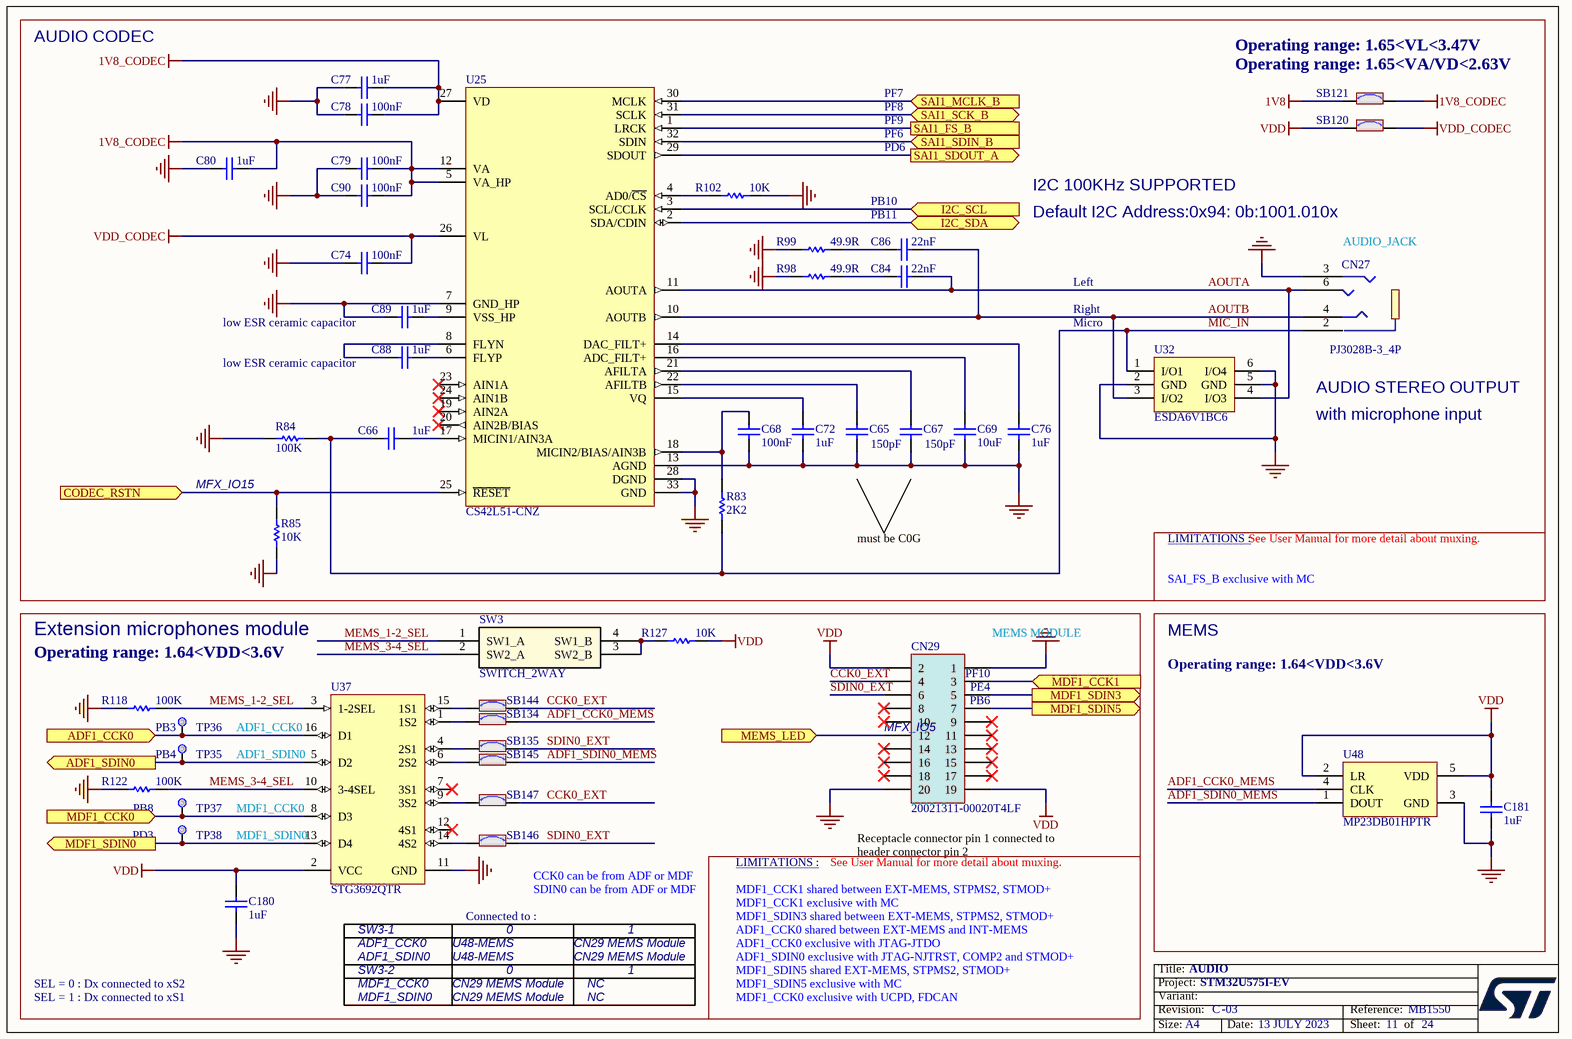
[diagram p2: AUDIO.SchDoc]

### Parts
C65  value 150pF  [C0603]
C66  value 1uF  [C0603]
C67  value 150pF  [C0603]
C68  value 100nF  [C0402]
C69  value 10uF  [C0402]  (hidden comment: Capacitor)
C72  value 1uF  [C0603]
C74  value 100nF  [C0402]
C76  value 1uF  [C0603]
C77  value 1uF  [C0603]
C78  value 100nF  [C0402]
C79  value 100nF  [C0402]
C80  value 1uF  [C0603]
C84  value 22nF  [C0603]
C86  value 22nF  [C0603]
C88  value 1uF  [C0603]
C89  value 1uF  [C0603]
C90  value 100nF  [C0402]
C180  value 1uF  [C0603]
C181  value 1uF  [C0603]
CN27  value PJ3028B-3_4P  [CON_PHONE-JACK-3P5_HY_PJ3028B]
CN29  value 20021311-00020T4LF  [CON_FCI_20021311-XXX20XXLF]
R83  value 2K2  [R0603]
R84  value 100K  [R0603]
R85  value 10K  [R0603]
R98  value 49.9R  [R0603]
R99  value 49.9R  [R0603]
R102  value 10K  [R0603]
R118  value 100K  [R0603]
R122  value 100K  [R0603]
R127  value 10K  [R0603]  (hidden comment: Resistor)
SB120  (no value)  [SOLDER-BRIDGE_R0603-0R]
SB121  (no value)  [SOLDER-BRIDGE_R0603-0R]
SB134  (no value)  [SOLDER-BRIDGE_R0603-0R]
SB135  (no value)  [SOLDER-BRIDGE_R0603-0R]
SB144  (no value)  [SOLDER-BRIDGE_R0603-0R]
SB145  (no value)  [SOLDER-BRIDGE_R0603-0R]
SB146  (no value)  [SOLDER-BRIDGE_R0603-0R]
SB147  (no value)  [SOLDER-BRIDGE_R0603-0R]
SW3  SWITCH_2WAY  [SWI_C&K_SDA02H1SBD_2POS]
TP35  value ADF1_SDIN0  [TP_SMD_1MM]  (no BOM)
TP36  value ADF1_CCK0  [TP_SMD_1MM]  (no BOM)
TP37  value MDF1_CCK0  [TP_SMD_1MM]  (no BOM)
TP38  value MDF1_SDIN0  [TP_SMD_1MM]  (no BOM)
U25  value CS42L51-CNZ  [ICC_QFN32-EPAD_5X5_P050]
U32  value ESDA6V1BC6  [ESD_SOT23-6L]
U37  STG3692QTR  [ICC_UFQFN16-EPAD_2P6X1P8_P040]
U48  value MP23DB01HPTR  [MIC_STM_MP23DB01MMTR]  (hidden comment: MP23DB01MMTR)

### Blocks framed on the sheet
Extension microphones module: C180 CN29 R118 R122 R127 SB134 SB135 SB144-SB147 SW3 TP35-TP38 U37
MEMS: C181 U48

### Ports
ADF1_CCK0 (in), ADF1_SDIN0 (out), CODEC_RSTN (in), I2C_SCL (in), I2C_SDA (bidir), MDF1_CCK0 (in), MDF1_CCK1 (in), MDF1_SDIN0 (out), MDF1_SDIN3 (out), MDF1_SDIN5 (out), MEMS_LED (in), SAI1_FS_B, SAI1_MCLK_B (in), SAI1_SCK_B (bidir), SAI1_SDIN_B (in), SAI1_SDOUT_A (out)

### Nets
1V8: SB121.1
1V8_CODEC: C77.2 C78.1 C79.1 C80.2 C90.1 SB121.2 U25.5(VA_HP) U25.12(VA) U25.27(VD)
GND: C65.2 C67.2 C68.2 C69.1 C72.1 C74.1 C76.1 C77.1 C78.2 C79.2 C80.1 C89.1 C90.2 C180.1 C181.2 CN27.3 CN29.1 CN29.20 R84.1 R85.1 R98.1 R99.1 R102.2 R118.2 R122.2 U25.7(GND_HP) U25.13(AGND) U25.28(DGND) U25.33(GND) U32.2(GND) U32.5(GND) U32.6(I/O4) U37.11(GND) U48.3(GND)
VDD: C180.2 C181.1 CN29.2 CN29.19 R127.2 SB120.1 U37.2(VCC) U48.2(LR) U48.5(VDD)
VDD_CODEC: C74.2 SB120.2 U25.26(VL)
ADF1_CCK0: TP36.1 U37.16(D1) ; port ADF1_CCK0
ADF1_CCK0_MEMS: SB134.2 U48.4(CLK)
ADF1_SDIN0: TP35.1 U37.5(D2) ; port ADF1_SDIN0
ADF1_SDIN0_MEMS: SB145.2 U48.1(DOUT)
AOUTA: C84.2 CN27.6 U25.11(AOUTA) U32.4(I/O3)
AOUTB: C86.2 CN27.4 U25.10(AOUTB) U32.3(I/O2)
CCK0_EXT: CN29.4 SB144.2 SB147.2
CODEC_RSTN: R85.2 U25.25(~{RESET}) ; port CODEC_RSTN
I2C_SCL: U25.3(SCL/CCLK) ; port I2C_SCL
I2C_SDA: U25.2(SDA/CDIN) ; port I2C_SDA
MDF1_CCK0: TP37.1 U37.8(D3) ; port MDF1_CCK0
MDF1_CCK1: CN29.3 ; port MDF1_CCK1
MDF1_SDIN0: TP38.1 U37.13(D4) ; port MDF1_SDIN0
MDF1_SDIN3: CN29.5 ; port MDF1_SDIN3
MDF1_SDIN5: CN29.7 ; port MDF1_SDIN5
MEMS_1-2_SEL: R118.1 SW3.1(SW1_A) U37.3(1-2SEL)
MEMS_3-4_SEL: R122.1 SW3.2(SW2_A) U37.10(3-4SEL)
MEMS_LED: CN29.12 ; port MEMS_LED
MIC_IN: C66.1 CN27.2 R83.1 R84.2 U32.1(I/O1)
SAI1_FS_B: U25.1(LRCK) ; port SAI1_FS_B
SAI1_MCLK_B: U25.30(MCLK) ; port SAI1_MCLK_B
SAI1_SCK_B: U25.31(SCLK) ; port SAI1_SCK_B
SAI1_SDIN_B: U25.32(SDIN) ; port SAI1_SDIN_B
SAI1_SDOUT_A: U25.29(SDOUT) ; port SAI1_SDOUT_A
SDIN0_EXT: CN29.6 SB135.2 SB146.2
NetC65_1: C65.1 U25.22(AFILTB)
NetC66_2: C66.2 U25.17(MICIN1/AIN3A)
NetC67_1: C67.1 U25.21(AFILTA)
NetC68_1: C68.1 R83.2 U25.18(MICIN2/BIAS/AIN3B)
NetC69_2: C69.2 U25.16(ADC_FILT+)
NetC72_2: C72.2 U25.15(VQ)
NetC76_2: C76.2 U25.14(DAC_FILT+)
NetC84_1: C84.1 R98.2
NetC86_1: C86.1 R99.2
NetC88_1: C88.1 U25.8(FLYN)
NetC88_2: C88.2 U25.6(FLYP)
NetC89_2: C89.2 U25.9(VSS_HP)
NetR102_1: R102.1 U25.4(AD0/~{CS})
NetR127_1: R127.1 SW3.3(SW2_B) SW3.4(SW1_B)
NetSB134_1: SB134.1 U37.1(1S2)
NetSB135_1: SB135.1 U37.4(2S1)
NetSB144_1: SB144.1 U37.15(1S1)
NetSB145_1: SB145.1 U37.6(2S2)
NetSB146_1: SB146.1 U37.14(4S2)
NetSB147_1: SB147.1 U37.9(3S2)

Not connected (* = marked no-connect by the designer): CN29 8* 9* 10* 11* 13* 14* 15* 16* 17* 18*; U25 19(AIN2A)* 20(AIN2B/BIAS)* 23(AIN1A)* 24(AIN1B)*; U37 7(3S1)* 12(4S1)*

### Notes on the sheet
- AUDIO CODEC
- PF8
- PF7
- (near SB121) Operating range: 1.65<VL<3.47V
  Operating range: 1.65<VA/VD<2.63V
- PF6
- PD6
- PF9
- PB10
- (near C86) PB11
- Default I2C Address:0x94: 0b:1001.010x
- I2C 100KHz SUPPORTED
- (near CN27) AUDIO_JACK
- Left
- Right
- low ESR ceramic capacitor
- (near C88) low ESR ceramic capacitor
- Micro
- (near CN27) AUDIO STEREO OUTPUT
- with microphone input
- MFX_IO15
- must be C0G
- LIMITATIONS :
- SAI_FS_B exclusive with MC
- See User Manual for more detail about muxing.
- (near CN29) MEMS MODULE
- Operating range: 1.64<VDD<3.6V
- (near CN29) PF10
- (near CN29) PE4
- (near CN29) PB6
- PB3
- (near TP35) PB4
- (near CN29) MFX_IO5
- PB8
- (near TP38) PD3
- (near CN29) Receptacle connector pin 1 connected to header connector pin 2
- Connected to :
- (near SB146) CCK0 can be from ADF or MDF
- (near SB146) SDIN0 can be from ADF or MDF
- MDF1_CCK1 shared between EXT-MEMS, STPMS2, STMOD+
- MDF1_CCK1 exclusive with MC
- MDF1_SDIN3 shared between EXT-MEMS, STPMS2, STMOD+
- SEL = 0 : Dx connected to xS2
- SW3-1
- ADF1_CCK0
- ADF1_SDIN0
- MDF1_CCK0
- SW3-2
- U48-MEMS
- CN29 MEMS Module
- 0
- NC
- 1
- ADF1_CCK0 shared between EXT-MEMS and INT-MEMS
- ADF1_CCK0 exclusive with JTAG-JTDO
- ADF1_SDIN0 exclusive with JTAG-NJTRST, COMP2 and STMOD+
- MDF1_SDIN5 shared EXT-MEMS, STPMS2, STMOD+
- MDF1_SDIN5 exclusive with MC
- SEL = 1 : Dx connected to xS1
- MDF1_SDIN0
- MDF1_CCK0 exclusive with UCPD, FDCAN

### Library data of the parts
C65 C67 = MCD-00304: Capacitor, MLCC, 150pF, 50V, COG, 5%, 0603, T=0,8mm; Manufacturer_Part_Number: CC0603JRNPO9BN151; Manufacturer: YAGEO; Provided_By: Subcon; Initial_Board_Reference: MB1263
C66 C72 C76 C77 C80 C88 C89 C180 C181 = MCD-00010: Capacitor, MLCC, 1uF, 16V, X5R, 10%, 0603, T=0,8mm; Manufacturer_Part_Number: CC0603KRX5R7BB105; Manufacturer: YAGEO; Provided_By: Subcon; Initial_Board_Reference: MB1274
C68 C74 C78 C79 C90 = MCD-00006: Capacitor, MLCC, 100nF, 16V, X7R, 10%, 0402, T=0.5mm; Manufacturer_Part_Number: CC0402KRX7R7BB104; Manufacturer: YAGEO; Alternate_Manufacturer_Part_Number: GCM155R71C104KA55D; Alternate_Manufacturer: MURATA; Provided_By: SUBCO; ECCN_US: EAR99; ECCN_EU: NEC
C69 = MCD-01355: Capacitor, MLCC, 10uF, 4V, X5R, 20%, 0402, T=0,5mm; Manufacturer_Part_Number: GRM155R60G106ME44; Manufacturer: MURATA; ECCN_US: EAR99; ECCN_EU: NEC; Provided_By: Subcon; Initial_Board_Reference: MB1372
C84 C86 = MCD-00555: Capacitor, MLCC, 22nF, 10%, 25V, X7R, 0603, T=0,8mm; Manufacturer_Part_Number: CC0603KRX7R8BB223; Manufacturer: YAGEO; Provided_By: Subcon; Initial_Board_Reference: MB1331
CN27 = MCD-00263: Connector Jack Socket Stereo 3.5mm, 4 pins, RA, SMT, Black; Manufacturer: QIAOD; Provided_By: Subcon; Initial_Board_Reference: MB1274
CN29 = MCD-00147: Socket, 10x2, 1.27mm, VR, TH, Height 4.30mm/2.40mm; Part_Type: Connector; Manufacturer: FCI; ECCN_US: EAR99; ECCN_EU: NEC; Provided_By: Subcon; Initial_Board_Reference: MB1262
R83 = MCD-00349: Resistor,2K2,0603,1%,1/10W; Manufacturer_Part_Number: RC0603FR-072K2L; Manufacturer: YAGEO; Provided_By: Subcon
R84 R118 R122 = MCD-00223: Resistor,100K,0603,1%,1/10W; Manufacturer_Part_Number: RC0603FR-07100KL; Manufacturer: YAGEO; Provided_By: Subcon; Initial_Board_Reference: MB1319
R85 R102 = MCD-00220: Resistor,10K,0603,1%,1/10W; Manufacturer_Part_Number: RC0603FR-0710KL; Manufacturer: YAGEO; Provided_By: Subcon; Initial_Board_Reference: MB1319
R98 R99 = MCD-00564: Resistor,49R9,0603,1%,1/10W; Manufacturer_Part_Number: RC0603FR-0749R9L; Manufacturer: YAGEO; Provided_By: Subcon; Initial_Board_Reference: MB1331
R127 = MCD-00220: Resistor,10K,0603,1%,1/10W; Manufacturer_Part_Number: RC0603FR-0710KL; Manufacturer: YAGEO; Provided_By: SUBCO; Initial_Board_Reference: MB1319; Item Type: Item; Path: ws/MCD_ApplicationBoards/Lists/MCDPARTSdatabase
SB120 SB121 SB134 SB135 SB144-SB147 = MCD-00071: Solder Bridge ON; Part_Type: Mechanical; Provided_By: Subcon; Initial_Board_Reference: MB1274
SW3 = MCD-00658: Dip Switch ,2Position ,Surface Mount Slide (Standard) ,2.54 pitch,25mA 24VDC; Part_Type: Misc; Manufacturer_Part_Number: SDA02H1SBD; Manufacturer: C&K; Provided_By: SUBCO
TP35-TP38 = MCD-00074: Test Point 1mm; Part_Type: Mechanical; Initial_Board_Reference: MB1274
U25 = MCD-00265: Low-Power, Stereo Codec with Headphone Amp; Manufacturer: CIRRUS LOGIC; Part_Type: IC; Provided_By: Subcon; ECCN_US: EAR99; ECCN_EU: NEC; Initial_Board_Reference: MB1272
U32 = MCD-00247: Quad Bidir ESD protection; Manufacturer: STMICROELECTRONICS; Part_Type: Diode; Provided_By: Subcon; ECCN_US: EAR99; ECCN_EU: NEC; Initial_Board_Reference: MB1311
U37 = MCD-00317: Low voltage high bandwidth quad SPDT switch; Part_Type: IC; Manufacturer: STMICROELECTRONICS; BMS_Part_Number: 9159018; ECCN_US: EAR99; ECCN_EU: NEC; Provided_By: SUBCO with ST control
U48 = MCD-02122: MEMS sensors , omnidirectionnal digital microphone; Part_Type: IC; Manufacturer: STMICROELECTRONICS; Manufacturer_HQ_COO: EU; Part_Preference: Recommended; Component_Country_Of_Origin: China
